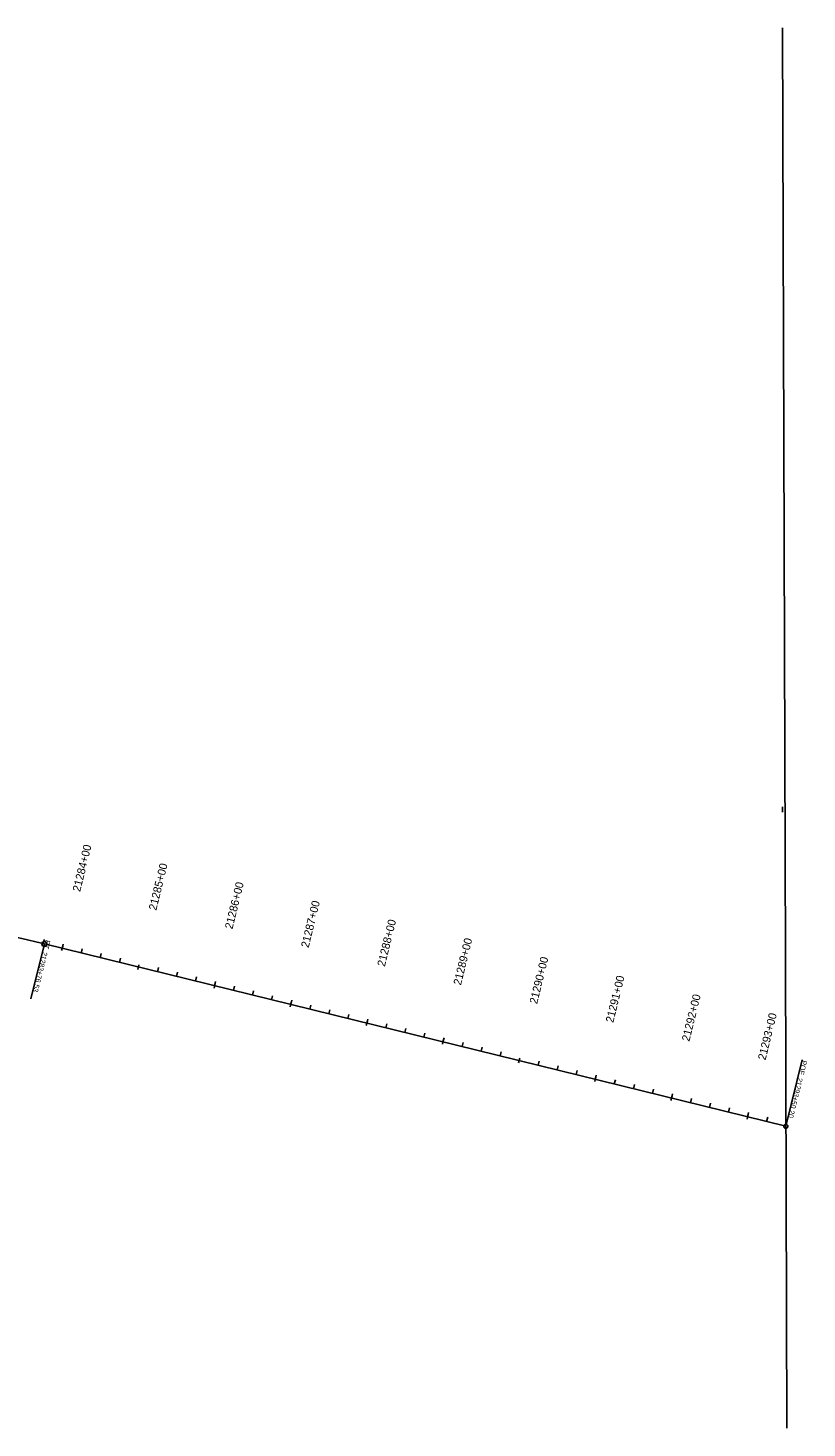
# Model space of a CAD drawing. Extents: x 18477855 to 18479805, y 7488250 to 7490035.
# Drawn here: x 18478811 to 18479805, y 7488250 to 7490035 of the extents above; entities that cross this region are included whole.
import ezdxf

# ---------------------------------------------------------------- set-up
doc = ezdxf.new("R2010")
doc.units = 0
for name, color, linetype in [('Default', 7, 'Continuous'), ('PhoSurveyLimits', 7, 'Continuous'), ('PhoTerrainContourMajor', 7, 'Continuous'), ('PhoTerrainContourMinor', 7, 'Continuous'), ('PhoTerrainTriangle', 7, 'Continuous'), ('Terrain', 7, 'Continuous')]:
    doc.layers.add(name, color=color, linetype=linetype)

msp = doc.modelspace()

# ---------------------------------------------------------------- linework, layer by layer
at = {"layer": 'Default'}
msp.add_line((18479773.2, 7489034.8), (18479773.2, 7489041.9), dxfattribs=at)
at = {"layer": 'PhoSurveyLimits'}
msp.add_arc((18478354.9, 7486924.7), 2000, 76.1977, 86.3864, dxfattribs=at)
at = {"layer": 'PhoTerrainContourMajor'}
for p, q in [((18478830.6, 7488867.3), (18478831.9, 7488872.6)), ((18478855.6, 7488864.3), (18478854.1, 7488858.4)), ((18478879.1, 7488855.4), (18478880.4, 7488860.7)), ((18478903.4, 7488849.4), (18478904.7, 7488854.7)), ((18478927.7, 7488843.4), (18478929, 7488848.7)), ((18478952.7, 7488840.4), (18478951.2, 7488834.5)), ((18478976.2, 7488831.5), (18478977.6, 7488836.8)), ((18479000.5, 7488825.5), (18479001.8, 7488830.8)), ((18479024.8, 7488819.6), (18479026.1, 7488824.9)), ((18479049.8, 7488816.6), (18479048.4, 7488810.6)), ((18479073.4, 7488807.7), (18479074.7, 7488813)), ((18479097.6, 7488801.7), (18479098.9, 7488807)), ((18479121.9, 7488795.7), (18479123.2, 7488801)), ((18479146.9, 7488792.7), (18479145.5, 7488786.8)), ((18479170.5, 7488783.8), (18479171.8, 7488789.1)), ((18479194.8, 7488777.8), (18479196.1, 7488783.1)), ((18479219, 7488771.9), (18479220.3, 7488777.2)), ((18479244, 7488768.9), (18479242.6, 7488762.9)), ((18479267.6, 7488759.9), (18479268.9, 7488765.2)), ((18479291.9, 7488754), (18479293.2, 7488759.3)), ((18479316.1, 7488748), (18479317.4, 7488753.3)), ((18479341.1, 7488745), (18479339.7, 7488739.1)), ((18479364.7, 7488736.1), (18479366, 7488741.4)), ((18479389, 7488730.1), (18479390.3, 7488735.4)), ((18479413.3, 7488724.2), (18479414.6, 7488729.5)), ((18479438.3, 7488721.2), (18479436.8, 7488715.2)), ((18479461.8, 7488712.2), (18479463.1, 7488717.5)), ((18479486.1, 7488706.3), (18479487.4, 7488711.6)), ((18479510.4, 7488700.3), (18479511.7, 7488705.6)), ((18479535.4, 7488697.3), (18479533.9, 7488691.4)), ((18479558.9, 7488688.4), (18479560.2, 7488693.7)), ((18479583.2, 7488682.4), (18479584.5, 7488687.7)), ((18479607.5, 7488676.4), (18479608.8, 7488681.7)), ((18479632.5, 7488673.4), (18479631, 7488667.5)), ((18479656, 7488664.5), (18479657.3, 7488669.8)), ((18479680.3, 7488658.5), (18479681.6, 7488663.8)), ((18479704.6, 7488652.6), (18479705.9, 7488657.9)), ((18479729.6, 7488649.6), (18479728.1, 7488643.6)), ((18479753.1, 7488640.7), (18479754.5, 7488646)), ((18479777.4, 7488634.7), (18479778.7, 7488640))]:
    msp.add_line(p, q, dxfattribs=at)
at = {"layer": 'PhoTerrainContourMinor'}
for p, q in [((18478832.1, 7488866.9), (18478814.9, 7488797)), ((18479777.6, 7488634.6), (18479798.4, 7488719.1))]:
    msp.add_line(p, q, dxfattribs=at)
for centre, radius in [((18478832.1, 7488866.9), 3.12), ((18479777.6, 7488634.6), 2.67)]:
    msp.add_circle(centre, radius, dxfattribs=at)
at = {"layer": 'PhoTerrainTriangle'}
for p, q in [((18478854.9, 7488861.3), (18478856.2, 7488866.6)), ((18478952.7, 7488840.4), (18478951.2, 7488834.5)), ((18479049.1, 7488813.6), (18479050.4, 7488818.9)), ((18479146.2, 7488789.8), (18479147.5, 7488795.1)), ((18479243.3, 7488765.9), (18479244.6, 7488771.2)), ((18479340.4, 7488742), (18479341.7, 7488747.3)), ((18479438.3, 7488721.2), (18479436.8, 7488715.2)), ((18479534.6, 7488694.3), (18479535.9, 7488699.6)), ((18479631.8, 7488670.5), (18479633.1, 7488675.8)), ((18479728.9, 7488646.6), (18479730.2, 7488651.9))]:
    msp.add_line(p, q, dxfattribs=at)
at = {"layer": 'Terrain'}
for p, q in [((18479777, 7488849.8), (18479773.5, 7490034.8)), ((18479777, 7488849.8), (18479773.5, 7490034.8)), ((18479777.6, 7488634.6), (18478832.1, 7488866.9)), ((18479777.6, 7488634.6), (18478832.1, 7488866.9)), ((18478832.1, 7488866.9), (18479777.6, 7488634.6)), ((18479777, 7488849.8), (18479778.7, 7488249.8)), ((18479778.7, 7488249.8), (18479777, 7488849.8))]:
    msp.add_line(p, q, dxfattribs=at)
msp.add_arc((18478354.9, 7486924.7), 2000, 76.1977, 86.3864, dxfattribs=at)

# ---------------------------------------------------------------- texts
at = {"layer": 'PhoTerrainContourMajor'}
for s, p in [('21284+00', (18478877.7, 7488932.9)), ('21285+00', (18478974.8, 7488909.1)), ('21286+00', (18479071.9, 7488885.2)), ('21287+00', (18479169, 7488861.4)), ('21288+00', (18479266.2, 7488837.5)), ('21289+00', (18479363.3, 7488813.7)), ('21290+00', (18479460.4, 7488789.8)), ('21291+00', (18479557.5, 7488765.9)), ('21292+00', (18479654.6, 7488742.1)), ('21293+00', (18479751.7, 7488718.2))]:
    msp.add_text(s, height=10.2, rotation=76.1977, dxfattribs=at).set_placement(p)
at = {"layer": 'PhoTerrainContourMinor'}
for s, p in [('PT', (18478833.6, 7488872.6)), ('21283+76.53', (18478829.9, 7488857.5)), ('POE ', (18479798.5, 7488719.1)), ('21293+50.20', (18479793, 7488696.9))]:
    msp.add_text(s, height=6.48, rotation=256.1977, dxfattribs=at).set_placement(p)
at = {"layer": 'PhoTerrainTriangle'}
for s, p in [('21285+00', (18478974.8, 7488909.1)), ('21290+00', (18479460.4, 7488789.8))]:
    msp.add_text(s, height=10.2, rotation=76.1977, dxfattribs=at).set_placement(p)

doc.saveas('drawing.dxf')
